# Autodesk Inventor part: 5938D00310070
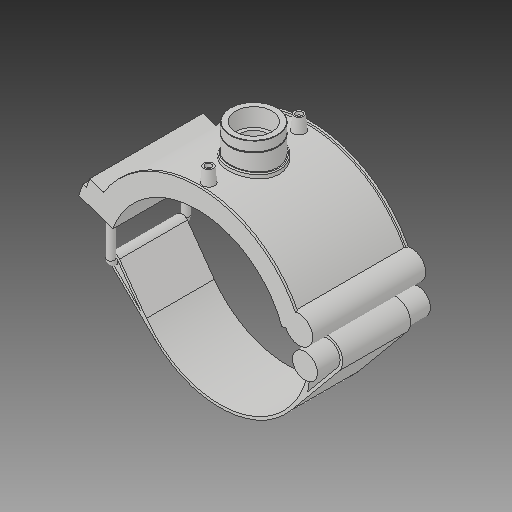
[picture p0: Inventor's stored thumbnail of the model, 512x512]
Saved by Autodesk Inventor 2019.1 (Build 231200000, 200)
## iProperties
Created: 2017-07
Part Number: 5938D00310070
Material: Generic
Description: PLASSON TRANSITION SADDLE 10''DIPS x 2"NPT
Document SubType Name: Modeling
Designer: KIM
Density: 1 g/cm^3
Appearance: Default
Author: KIM
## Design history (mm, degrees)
derived "5938D.ipt"
feature "Solid1::5938D.ipt"
tag "TaggingFeature1"
body "Solid1"
other parameters: "d_" = 280.6, "B_" = 180.34, "H_" = 46.736, "L_" = 176.022, "d_t" = 6, "G_" = 56.656, "d148" = 4.209, "d160" = 4.209, "d169" = 4.209, "d192" = 11.224, "d0" = 280.6, "d1" = 336.72, "d2" = 450.85, "d3" = 70.15, "d4" = 176.022, "d5" = 0, "d40" = 175.0944, "d41" = 79.3184, "d43" = 0, "d45" = 0, "d47" = 215.096, "d48" = 73.6528, "d50" = 0, "d78" = 190.36, "d79" = 15, "d80" = 70.4088, "d82" = 5 deg, "d84" = 4, "d85" = 14, "d86" = 0, "d87" = 3, "d88" = 0, "d96" = 343.4544, "d97" = 3.52044, "d98" = 0, "d102" = 1.69968, "d103" = 56.656, "d104" = 28.0416, "d105" = 0, "d106" = 45.3248, "d108" = 0, "d109" = -15.57867, "d111" = 0.5, "d112" = 0.5, "d113" = 0, "d114" = 0.5, "d117" = 0.56656, "d120" = 140 deg, "d121" = 24.228, "d122" = 20 deg, "d123" = 1346.88, "d124" = 202.032, "d126" = 0, "d143" = 289.018, "d145" = 43.16923, "d149" = 4.209, "d150" = 47.48615, "d153" = 176.022, "d154" = 0, "d156" = 168.36, "d157" = 160 deg, "d159" = 11.224, "d161" = 4.209, "d162" = 105.6132, "d163" = 0, "d164" = 140.3, "d167" = 28.06, "d168" = 164.25366, "d170" = 4.209, "d172" = 0, "d173" = 1, "d175" = 140.3, "d176" = 20 deg, "d177" = 19.642, "d178" = 56.12, "d180" = 0, "d183" = 22.448, "d184" = 15.7136, "d185" = 57.20715, "d186" = 57.20715, "d187" = 168.36, "d188" = 16.836, "d189" = 19.642, "d190" = 0, "d191" = 202.032, "d193" = 11.224, "d194" = 5.7523, "d195" = 90 deg, "d197" = 0, "d199" = 0
